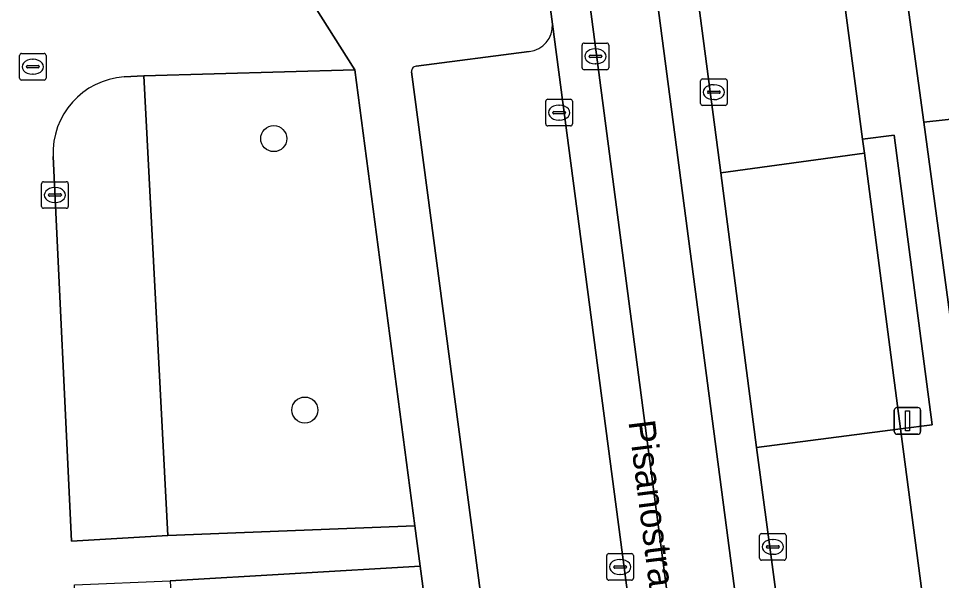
# Model space of a CAD drawing. Extents: x 160554 to 161248, y 385329 to 386506.
# Drawn here: x 161127.39 to 161162.07, y 385431.46 to 385452.59 of the extents above; entities that cross this region are included whole.
import ezdxf

# ---------------------------------------------------------------- set-up
doc = ezdxf.new("R2010")
doc.units = 0
for name, color, linetype in [('IMGEO_Boom', 7, 'Continuous'), ('IMGEO_Groenvoorziening', 7, 'Continuous'), ('IMGEO_Haag', 7, 'Continuous'), ('IMGEO_Kolk', 7, 'Continuous'), ('IMGEO_Lichtmast', 7, 'Continuous'), ('IMGEO_Openbare_ruimte_label', 7, 'Continuous'), ('IMGEO_Parkeervlak_open', 7, 'Continuous'), ('IMGEO_Rijbaan_lokaal_gesloten', 7, 'Continuous'), ('IMGEO_Rijbaan_lokaal_open', 7, 'Continuous'), ('IMGEO_Rioolput', 7, 'Continuous'), ('IMGEO_Voetpad_open', 7, 'Continuous')]:
    doc.layers.add(name, color=color, linetype=linetype)

msp = doc.modelspace()

# ---------------------------------------------------------------- linework, layer by layer
at = {"layer": 'IMGEO_Boom'}
for centre in [(161136.982, 385448.072), (161138.15, 385437.867)]:
    msp.add_circle(centre, 0.489, dxfattribs=at)
at = {"layer": 'IMGEO_Groenvoorziening'}
for points in [[(161161.406, 385448.688), (161164.503, 385449.031), (161163.696, 385455.083), (161160.609, 385454.566)], [(161132.098, 385450.427), (161133.001, 385433.144), (161142.282, 385433.518), (161140.025, 385450.66)], [(161133.09, 385431.445), (161133.947, 385415.029), (161143.422, 385415.333), (161144.689, 385415.374), (161142.478, 385431.994)]]:
    msp.add_lwpolyline(points, close=True, dxfattribs=at)
for points in [[(161128.694, 385447.4), (161129.379, 385432.942), (161133.001, 385433.144), (161132.098, 385450.427)], [(161132.098, 385450.427), (161132.098, 385450.431), (161131.359, 385450.395)]]:
    msp.add_lwpolyline(points, dxfattribs=at)
msp.add_arc((161131.557, 385447.535), 2.867, 93.9687, 182.7049, dxfattribs=at)
at = {"layer": 'IMGEO_Haag'}
msp.add_lwpolyline([(161161.406, 385448.688), (161164.503, 385449.031), (161163.696, 385455.083), (161160.609, 385454.566)], close=True, dxfattribs=at)
at = {"layer": 'IMGEO_Kolk'}
for p, q in [((161153.018, 385449.393), (161153.018, 385450.245)), ((161153.093, 385450.319), (161153.945, 385450.319)), ((161153.506, 385450.099), (161153.531, 385450.099)), ((161154.019, 385450.245), (161154.019, 385449.393)), ((161153.277, 385449.813), (161153.277, 385449.825)), ((161153.715, 385449.776), (161153.317, 385449.776)), ((161153.32, 385449.862), (161153.718, 385449.862)), ((161153.761, 385449.825), (161153.761, 385449.813)), ((161147.204, 385448.624), (161147.204, 385449.476)), ((161147.279, 385449.55), (161148.131, 385449.55)), ((161148.205, 385449.476), (161148.205, 385448.624)), ((161153.529, 385449.539), (161153.504, 385449.539)), ((161147.463, 385449.044), (161147.463, 385449.056)), ((161147.901, 385449.007), (161147.503, 385449.007)), ((161147.506, 385449.093), (161147.904, 385449.093)), ((161147.692, 385449.33), (161147.717, 385449.33)), ((161147.947, 385449.056), (161147.947, 385449.044)), ((161153.945, 385449.319), (161153.093, 385449.319)), ((161147.715, 385448.77), (161147.69, 385448.77)), ((161148.131, 385448.55), (161147.279, 385448.55)), ((161128.261, 385445.526), (161128.261, 385446.378)), ((161128.336, 385446.452), (161129.188, 385446.452)), ((161128.749, 385446.232), (161128.774, 385446.232)), ((161129.262, 385446.378), (161129.262, 385445.526)), ((161128.52, 385445.946), (161128.52, 385445.958)), ((161128.958, 385445.909), (161128.56, 385445.909)), ((161128.563, 385445.995), (161128.961, 385445.995)), ((161129.004, 385445.958), (161129.004, 385445.946)), ((161128.772, 385445.672), (161128.747, 385445.672)), ((161129.188, 385445.452), (161128.336, 385445.452)), ((161155.234, 385432.296), (161155.234, 385433.148)), ((161155.309, 385433.222), (161156.161, 385433.222)), ((161156.235, 385433.148), (161156.235, 385432.296)), ((161155.493, 385432.716), (161155.493, 385432.728)), ((161155.536, 385432.765), (161155.934, 385432.765)), ((161155.722, 385433.002), (161155.747, 385433.002)), ((161155.977, 385432.728), (161155.977, 385432.716)), ((161149.496, 385431.542), (161149.496, 385432.394)), ((161149.571, 385432.468), (161150.423, 385432.468)), ((161150.497, 385432.394), (161150.497, 385431.542)), ((161155.931, 385432.679), (161155.533, 385432.679)), ((161155.745, 385432.442), (161155.72, 385432.442)), ((161149.798, 385432.011), (161150.196, 385432.011)), ((161149.984, 385432.248), (161150.009, 385432.248)), ((161156.161, 385432.222), (161155.309, 385432.222)), ((161149.755, 385431.962), (161149.755, 385431.974)), ((161150.193, 385431.925), (161149.795, 385431.925)), ((161150.007, 385431.688), (161149.982, 385431.688)), ((161150.239, 385431.974), (161150.239, 385431.962)), ((161150.423, 385431.468), (161149.571, 385431.468))]:
    msp.add_line(p, q, dxfattribs=at)
for points in [[(161153.018, 385449.393), (161153.018, 385450.245)], [(161153.093, 385450.319), (161153.945, 385450.319)], [(161154.019, 385450.245), (161154.019, 385449.393)], [(161147.204, 385448.624), (161147.204, 385449.476)], [(161147.279, 385449.55), (161148.131, 385449.55)], [(161148.205, 385449.476), (161148.205, 385448.624)], [(161153.945, 385449.319), (161153.093, 385449.319)], [(161148.131, 385448.55), (161147.279, 385448.55)], [(161128.261, 385445.526), (161128.261, 385446.378)], [(161128.336, 385446.452), (161129.188, 385446.452)], [(161129.262, 385446.378), (161129.262, 385445.526)], [(161129.188, 385445.452), (161128.336, 385445.452)], [(161155.234, 385432.296), (161155.234, 385433.148)], [(161155.309, 385433.222), (161156.161, 385433.222)], [(161156.235, 385433.148), (161156.235, 385432.296)], [(161149.496, 385431.542), (161149.496, 385432.394)], [(161149.571, 385432.468), (161150.423, 385432.468)], [(161150.497, 385432.394), (161150.497, 385431.542)], [(161156.161, 385432.222), (161155.309, 385432.222)], [(161150.423, 385431.468), (161149.571, 385431.468)]]:
    msp.add_lwpolyline(points, dxfattribs=at)
for centre, radius, start, end in [((161153.095, 385450.243), 0.0765, 91.552, 178.448), ((161153.095, 385450.243), 0.0765, 91.552, 178.448), ((161153.943, 385450.243), 0.0765, 1.552, 88.448), ((161153.943, 385450.243), 0.0765, 1.552, 88.448), ((161153.317, 385449.822), 0.0403, 85.8775, 175.7526), ((161153.314, 385449.812), 0.0366, 178.938, 274.7102), ((161153.718, 385449.819), 0.043, 264.8664, 352.4533), ((161153.722, 385449.824), 0.0386, 1.7309, 96.639), ((161147.281, 385449.474), 0.0765, 91.552, 178.448), ((161147.281, 385449.474), 0.0765, 91.552, 178.448), ((161148.129, 385449.474), 0.0765, 1.552, 88.448), ((161148.129, 385449.474), 0.0765, 1.552, 88.448), ((161153.095, 385449.395), 0.0765, 181.552, 268.448), ((161153.095, 385449.395), 0.0765, 181.552, 268.448), ((161153.943, 385449.395), 0.0765, 271.552, 358.448), ((161153.943, 385449.395), 0.0765, 271.552, 358.448), ((161147.503, 385449.053), 0.0403, 85.8775, 175.7526), ((161147.5, 385449.043), 0.0366, 178.938, 274.7102), ((161147.904, 385449.05), 0.043, 264.8664, 352.4533), ((161147.908, 385449.055), 0.0386, 1.7309, 96.639), ((161147.281, 385448.626), 0.0765, 181.552, 268.448), ((161147.281, 385448.626), 0.0765, 181.552, 268.448), ((161148.129, 385448.626), 0.0765, 271.552, 358.448), ((161148.129, 385448.626), 0.0765, 271.552, 358.448), ((161128.338, 385446.376), 0.0765, 91.552, 178.448), ((161128.338, 385446.376), 0.0765, 91.552, 178.448), ((161129.186, 385446.376), 0.0765, 1.552, 88.448), ((161129.186, 385446.376), 0.0765, 1.552, 88.448), ((161128.56, 385445.955), 0.0403, 85.8775, 175.7526), ((161128.557, 385445.945), 0.0366, 178.938, 274.7102), ((161128.961, 385445.952), 0.043, 264.8664, 352.4533), ((161128.965, 385445.957), 0.0386, 1.7309, 96.639), ((161128.338, 385445.528), 0.0765, 181.552, 268.448), ((161128.338, 385445.528), 0.0765, 181.552, 268.448), ((161129.186, 385445.528), 0.0765, 271.552, 358.448), ((161129.186, 385445.528), 0.0765, 271.552, 358.448), ((161155.311, 385433.146), 0.0765, 91.552, 178.448), ((161155.311, 385433.146), 0.0765, 91.552, 178.448), ((161156.159, 385433.146), 0.0765, 1.552, 88.448), ((161156.159, 385433.146), 0.0765, 1.552, 88.448), ((161155.533, 385432.725), 0.0403, 85.8775, 175.7526), ((161155.53, 385432.715), 0.0366, 178.938, 274.7102), ((161155.934, 385432.722), 0.043, 264.8664, 352.4533), ((161155.938, 385432.727), 0.0386, 1.7309, 96.639), ((161149.573, 385432.392), 0.0765, 91.552, 178.448), ((161149.573, 385432.392), 0.0765, 91.552, 178.448), ((161150.421, 385432.392), 0.0765, 1.552, 88.448), ((161150.421, 385432.392), 0.0765, 1.552, 88.448), ((161149.795, 385431.971), 0.0403, 85.8775, 175.7526), ((161150.2, 385431.973), 0.0386, 1.7309, 96.639), ((161155.311, 385432.298), 0.0765, 181.552, 268.448), ((161155.311, 385432.298), 0.0765, 181.552, 268.448), ((161156.159, 385432.298), 0.0765, 271.552, 358.448), ((161156.159, 385432.298), 0.0765, 271.552, 358.448), ((161149.792, 385431.961), 0.0366, 178.938, 274.7102), ((161150.196, 385431.968), 0.043, 264.8664, 352.4533), ((161149.573, 385431.544), 0.0765, 181.552, 268.448), ((161149.573, 385431.544), 0.0765, 181.552, 268.448), ((161150.421, 385431.544), 0.0765, 271.552, 358.448), ((161150.421, 385431.544), 0.0765, 271.552, 358.448)]:
    msp.add_arc(centre, radius, start, end, dxfattribs=at)
for centre, major_axis, ratio, start_param, end_param in [((161153.505, 385449.819), (-0.387, 0.002), 0.722429, 4.712389, 7.853982), ((161153.53, 385449.819), (-0.39, 0.002), 0.717154, 1.570796, 4.712389), ((161147.691, 385449.05), (-0.387, 0.002), 0.722429, 4.712389, 7.853982), ((161147.716, 385449.05), (-0.39, 0.002), 0.717154, 1.570796, 4.712389), ((161128.748, 385445.952), (-0.387, 0.002), 0.722429, 4.712389, 7.853982), ((161128.773, 385445.952), (-0.39, 0.002), 0.717154, 1.570796, 4.712389), ((161155.721, 385432.722), (-0.387, 0.002), 0.722429, 4.712389, 7.853982), ((161155.746, 385432.722), (-0.39, 0.002), 0.717154, 1.570796, 4.712389), ((161149.983, 385431.968), (-0.387, 0.002), 0.722429, 4.712389, 7.853982), ((161150.008, 385431.968), (-0.39, 0.002), 0.717154, 1.570796, 4.712389)]:
    msp.add_ellipse(centre, major_axis=major_axis, ratio=ratio, start_param=start_param, end_param=end_param, dxfattribs=at)
at = {"layer": 'IMGEO_Lichtmast'}
for p, q in [((161160.398, 385437.958), (161161.188, 385437.958)), ((161161.188, 385437.958), (161160.398, 385437.958)), ((161160.298, 385437.058), (161160.298, 385437.858)), ((161160.298, 385437.858), (161160.298, 385437.058)), ((161161.288, 385437.858), (161161.288, 385437.058)), ((161161.288, 385437.058), (161161.288, 385437.858)), ((161161.188, 385436.958), (161160.398, 385436.958)), ((161160.398, 385436.958), (161161.188, 385436.958))]:
    msp.add_line(p, q, dxfattribs=at)
msp.add_lwpolyline([(161160.718, 385437.833), (161160.868, 385437.833), (161160.868, 385437.083), (161160.718, 385437.083), (161160.718, 385437.833)], dxfattribs=at)
for centre, start, end in [((161160.398, 385437.858), 90, 180), ((161160.398, 385437.858), 90, 180), ((161161.188, 385437.858), 0, 90), ((161161.188, 385437.858), 360, 90), ((161160.398, 385437.058), 180, 270), ((161160.398, 385437.058), 180, 270), ((161161.188, 385437.058), 270, 0), ((161161.188, 385437.058), 270, 0)]:
    msp.add_arc(centre, 0.1, start, end, dxfattribs=at)
at = {"layer": 'IMGEO_Parkeervlak_open'}
for points in [[(161157.932, 385457), (161157.877, 385457.424), (161152.481, 385456.711), (161153.775, 385446.792), (161159.176, 385447.522), (161159.107, 385448.046)], [(161160.536, 385437.158), (161155.115, 385436.464), (161156.18, 385428.499), (161161.571, 385429.258)]]:
    msp.add_lwpolyline(points, close=True, dxfattribs=at)
for points in [[(161152.332, 385415.422), (161147.451, 385452.38)], [(161146.585, 385451.346), (161142.329, 385450.792)], [(161142.158, 385450.588), (161146.754, 385415.839)]]:
    msp.add_lwpolyline(points, dxfattribs=at)
for centre, radius, start, end in [((161146.471, 385452.321), 0.982, 276.6804, 3.4256), ((161142.338, 385450.611), 0.181, 92.786, 187.2721)]:
    msp.add_arc(centre, radius, start, end, dxfattribs=at)
at = {"layer": 'IMGEO_Rijbaan_lokaal_gesloten'}
for points in [[(161153.775, 385446.792), (161152.481, 385456.711), (161151.406, 385464.746), (161150.547, 385470.862), (161149.1, 385470.664), (161149.104, 385470.631), (161155.925, 385418.758)], [(161148.041, 385459.357), (161146.58, 385470.323), (161145.077, 385470.113), (161146.64, 385458.491), (161146.649, 385458.427), (161147.451, 385452.38), (161152.332, 385415.422), (161152.671, 385412.934), (161153.279, 385407.691), (161153.691, 385403.544)], [(161154.482, 385410.25), (161148.041, 385459.357)], [(161158.334, 385411.805), (161156.615, 385424.878), (161156.18, 385428.499), (161155.115, 385436.464), (161153.775, 385446.792)]]:
    msp.add_lwpolyline(points, dxfattribs=at)
at = {"layer": 'IMGEO_Rijbaan_lokaal_open'}
for points in [[(161149.104, 385470.631), (161146.58, 385470.323), (161148.041, 385459.357), (161154.482, 385410.25)], [(161155.925, 385418.758), (161149.104, 385470.631)]]:
    msp.add_lwpolyline(points, dxfattribs=at)
for points in [[(161162.864, 385437.938), (161165.924, 385438.385), (161164.503, 385449.031), (161161.406, 385448.688)], [(161159.176, 385447.522), (161153.775, 385446.792), (161155.115, 385436.464), (161160.536, 385437.158)]]:
    msp.add_lwpolyline(points, close=True, dxfattribs=at)
at = {"layer": 'IMGEO_Rioolput'}
for p, q in [((161148.57, 385450.739), (161148.57, 385451.591)), ((161148.645, 385451.665), (161149.497, 385451.665)), ((161149.058, 385451.445), (161149.083, 385451.445)), ((161149.571, 385451.591), (161149.571, 385450.739)), ((161127.429, 385450.348), (161127.429, 385451.2)), ((161127.504, 385451.274), (161128.356, 385451.274)), ((161128.43, 385451.2), (161128.43, 385450.348)), ((161148.829, 385451.159), (161148.829, 385451.171)), ((161149.267, 385451.122), (161148.869, 385451.122)), ((161148.872, 385451.208), (161149.27, 385451.208)), ((161149.313, 385451.171), (161149.313, 385451.159)), ((161127.688, 385450.768), (161127.688, 385450.78)), ((161128.126, 385450.731), (161127.728, 385450.731)), ((161127.731, 385450.817), (161128.129, 385450.817)), ((161127.917, 385451.054), (161127.942, 385451.054)), ((161128.172, 385450.78), (161128.172, 385450.768)), ((161149.081, 385450.885), (161149.056, 385450.885)), ((161127.94, 385450.494), (161127.915, 385450.494)), ((161149.497, 385450.665), (161148.645, 385450.665)), ((161128.356, 385450.274), (161127.504, 385450.274))]:
    msp.add_line(p, q, dxfattribs=at)
for points in [[(161148.57, 385450.739), (161148.57, 385451.591)], [(161148.645, 385451.665), (161149.497, 385451.665)], [(161149.571, 385451.591), (161149.571, 385450.739)], [(161127.429, 385450.348), (161127.429, 385451.2)], [(161127.504, 385451.274), (161128.356, 385451.274)], [(161128.43, 385451.2), (161128.43, 385450.348)], [(161149.497, 385450.665), (161148.645, 385450.665)], [(161128.356, 385450.274), (161127.504, 385450.274)]]:
    msp.add_lwpolyline(points, dxfattribs=at)
for centre, radius, start, end in [((161148.647, 385451.589), 0.0765, 91.552, 178.448), ((161148.647, 385451.589), 0.0765, 91.552, 178.448), ((161149.495, 385451.589), 0.0765, 1.552, 88.448), ((161149.495, 385451.589), 0.0765, 1.552, 88.448), ((161127.506, 385451.198), 0.0765, 91.552, 178.448), ((161127.506, 385451.198), 0.0765, 91.552, 178.448), ((161128.354, 385451.198), 0.0765, 1.552, 88.448), ((161128.354, 385451.198), 0.0765, 1.552, 88.448), ((161148.869, 385451.168), 0.0403, 85.8775, 175.7526), ((161148.866, 385451.158), 0.0366, 178.938, 274.7102), ((161149.27, 385451.165), 0.043, 264.8664, 352.4533), ((161149.274, 385451.17), 0.0386, 1.7309, 96.639), ((161127.728, 385450.777), 0.0403, 85.8775, 175.7526), ((161127.725, 385450.767), 0.0366, 178.938, 274.7102), ((161128.129, 385450.774), 0.043, 264.8664, 352.4533), ((161128.133, 385450.779), 0.0386, 1.7309, 96.639), ((161148.647, 385450.741), 0.0765, 181.552, 268.448), ((161148.647, 385450.741), 0.0765, 181.552, 268.448), ((161149.495, 385450.741), 0.0765, 271.552, 358.448), ((161149.495, 385450.741), 0.0765, 271.552, 358.448), ((161127.506, 385450.35), 0.0765, 181.552, 268.448), ((161127.506, 385450.35), 0.0765, 181.552, 268.448), ((161128.354, 385450.35), 0.0765, 271.552, 358.448), ((161128.354, 385450.35), 0.0765, 271.552, 358.448)]:
    msp.add_arc(centre, radius, start, end, dxfattribs=at)
for centre, major_axis, ratio, start_param, end_param in [((161149.057, 385451.165), (-0.387, 0.002), 0.722429, 4.712389, 7.853982), ((161149.082, 385451.165), (-0.39, 0.002), 0.717154, 1.570796, 4.712389), ((161127.916, 385450.774), (-0.387, 0.002), 0.722429, 4.712389, 7.853982), ((161127.941, 385450.774), (-0.39, 0.002), 0.717154, 1.570796, 4.712389)]:
    msp.add_ellipse(centre, major_axis=major_axis, ratio=ratio, start_param=start_param, end_param=end_param, dxfattribs=at)
at = {"layer": 'IMGEO_Voetpad_open'}
for points in [[(161164.772, 385423.865), (161164.522, 385425.705), (161163.706, 385431.728), (161162.864, 385437.938), (161161.406, 385448.688), (161160.609, 385454.566), (161158.742, 385468.334), (161157.96, 385474.333), (161156.587, 385484.87), (161155.775, 385491.088), (161154.612, 385500), (161153.977, 385504.866), (161153.181, 385510.938), (161151.795, 385521.505)], [(161156.157, 385470.407), (161156.758, 385465.935), (161157.954, 385466.094), (161159.145, 385457.161), (161157.932, 385457), (161159.107, 385448.046), (161160.298, 385448.2), (161161.726, 385437.317), (161160.536, 385437.158), (161161.571, 385429.258), (161162.77, 385429.42), (161163.288, 385425.403), (161162.096, 385425.252), (161163.599, 385413.775)], [(161147.451, 385452.38), (161146.649, 385458.427), (161146.64, 385458.491)], [(161131.359, 385450.395), (161132.098, 385450.431), (161132.098, 385450.427), (161140.025, 385450.66), (161138.04, 385453.815), (161103.911, 385452.001), (161104.086, 385449), (161122.774, 385449.889)], [(161138.04, 385453.815), (161140.025, 385450.66), (161142.282, 385433.518), (161142.478, 385431.994), (161144.689, 385415.374), (161144.425, 385412.29)], [(161142.329, 385450.792), (161146.585, 385451.346)], [(161146.754, 385415.839), (161142.158, 385450.588)], [(161130.247, 385417.539), (161129.491, 385431.291), (161133.09, 385431.445), (161142.478, 385431.994), (161142.282, 385433.518), (161133.001, 385433.144), (161129.379, 385432.942), (161128.694, 385447.4)]]:
    msp.add_lwpolyline(points, dxfattribs=at)
msp.add_lwpolyline([(161159.107, 385448.046), (161159.176, 385447.522), (161160.536, 385437.158), (161161.726, 385437.317), (161160.298, 385448.2)], close=True, dxfattribs=at)
for centre, radius, start, end in [((161146.471, 385452.321), 0.982, 276.6804, 3.4256), ((161142.338, 385450.611), 0.181, 92.786, 187.2721), ((161131.557, 385447.535), 2.867, 93.9687, 182.7049)]:
    msp.add_arc(centre, radius, start, end, dxfattribs=at)

# ---------------------------------------------------------------- texts
at = {"layer": 'IMGEO_Openbare_ruimte_label'}
msp.add_text('Pisanostraat', height=1, rotation=277.1819, dxfattribs=at).set_placement((161150.307, 385437.431))

doc.saveas('drawing.dxf')
